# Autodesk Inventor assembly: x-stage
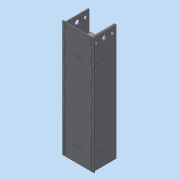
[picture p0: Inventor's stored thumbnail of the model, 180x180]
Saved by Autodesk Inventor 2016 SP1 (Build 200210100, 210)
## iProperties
Created: 2016-06
Part Number: x-stage
Document SubType Name: Assembly
Designer: Mohamed A.
Author: Mohamed A.
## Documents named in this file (7)
- C:\Users\Mohamed\Documents\inventor\machine_design\x-stage\x-stage.iam
- C:\Users\Mohamed\Documents\inventor\machine_design\stepper\body-box.ipt
- C:\Users\Mohamed\Documents\inventor\machine_design\x-stage\stepper-mount.ipt
- C:\Users\Mohamed\Documents\inventor\machine_design\x-stage\side.ipt
- C:\Users\Mohamed\Documents\inventor\machine_design\x-stage\side_outer.ipt
- C:\Users\Mohamed\Documents\inventor\machine_design\x-stage\back.ipt
- C:\Users\Mohamed\Documents\inventor\machine_design\x-stage\top.ipt
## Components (7 placed, 6 different names)
1. body-box:1 — Mate:1, Mate:2, Mate:3, Mate:4
2. stepper-mount:1 — Mate:1, Mate:2, Mate:3, Mate:4, Mate:5, Mate:6, Mate:7, Mate:8
3. side:1 — Mate:5, Mate:6, Mate:7, Flush:1, Flush:2, Flush:3, Mate:9, Flush:4, Flush:7
4. side:2 — Flush:1, Flush:2, Mate:8, Flush:6
5. side_outer:1 — Flush:3, Mate:9, Flush:4, Mate:10, Flush:8
6. back:1 — Flush:6, Flush:7, Mate:10, Flush:9
7. top:1 — Flush:8, Flush:9
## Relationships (18: Mate 10, Flush 8)
- Mate:1: body-box:1 ↔ stepper-mount:1
- Mate:2: body-box:1 ↔ stepper-mount:1
- Mate:3: body-box:1 ↔ stepper-mount:1
- Mate:4: body-box:1 ↔ stepper-mount:1
- Mate:5: stepper-mount:1 ↔ side:1
- Mate:6: stepper-mount:1 ↔ side:1
- Mate:7: stepper-mount:1 ↔ side:1
- Flush:1: side:1 ↔ side:2
- Flush:2: side:1 ↔ side:2
- Mate:8: stepper-mount:1 ↔ side:2
- Flush:3: side:1 ↔ side_outer:1
- Mate:9: side:1 ↔ side_outer:1
- Flush:4: side:1 ↔ side_outer:1
- Flush:6: side:2 ↔ back:1
- Flush:7: side:1 ↔ back:1
- Mate:10: side_outer:1 ↔ back:1
- Flush:8: side_outer:1 ↔ top:1
- Flush:9: back:1 ↔ top:1
